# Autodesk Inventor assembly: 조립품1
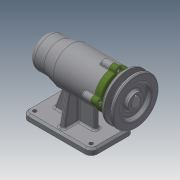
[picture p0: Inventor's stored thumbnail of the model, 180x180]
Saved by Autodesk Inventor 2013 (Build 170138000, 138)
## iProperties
Created: 2019-07
Part Number: 조립품1
Document SubType Name: Assembly
Designer: a
Author: a
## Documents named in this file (12)
- C:\Users\a\Desktop\490704V1048\조립품1.iam
- C:\Users\a\Desktop\490704V1048\본체.ipt
- C:\Users\a\Desktop\490704V1048\V벨트풀리.ipt
- C:\Users\a\Desktop\490704V1048\멈춤나사 M3.ipt
- C:\Users\a\Desktop\490704V1048\베어링 6004.ipt
- C:\Users\a\Desktop\490704V1048\베어링 51202.ipt
- C:\Users\a\Desktop\490704V1048\볼트 M4.ipt
- C:\Users\a\Desktop\490704V1048\어댑터슬리브.ipt
- C:\Users\a\Desktop\490704V1048\오일 실.ipt
- C:\Users\a\Desktop\490704V1048\축.ipt
- C:\Users\a\Desktop\490704V1048\커버.ipt
- C:\Users\a\Desktop\490704V1048\키 5 x 5 x 16.ipt
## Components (1 placed, 1 different names)
1. V벨트풀리:1 — 플러쉬:1
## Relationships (1: Flush 1)
- 플러쉬:1 [Flush]: V벨트풀리:1
